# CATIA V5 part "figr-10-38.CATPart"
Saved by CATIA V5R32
Part number: Part1
Bounding box of the stored display mesh (mm): x -94.328 to 61.591, y -127.491 to 0, z 0 to 176.047
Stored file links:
  D:\PROJECTS\Project 2022\CATIA V5 6R 2022\Resources\Part Files\c10_catia_v5_6r2022_prt\c10_catia_v5_6r2022_prt\figr-10-38.CATPart
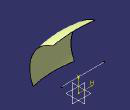
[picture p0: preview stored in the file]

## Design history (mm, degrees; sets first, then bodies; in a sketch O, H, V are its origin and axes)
Body1 (main body)
  Sketch1 on zx-plane, origin (0, 0, 0), H (-1, 0, 0), V (0, 0, 1)
    line L1 (-61.5909, 52.3674) -> (94.3285, 52.3674)
    horizontal: L1 H
  Sketch2 on xy-plane, origin (0, 0, 0), H (1, 0, 0), V (0, 1, 0)
    spline S1 through (-163.8621, -89.1589) (-19.9449, -116.4274) (134.5767, -79.3119)
  Sweep1: type Circle, Guide Sketch1, Reference Sketch2, Radius 100, Angle1 0, Angle2 100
